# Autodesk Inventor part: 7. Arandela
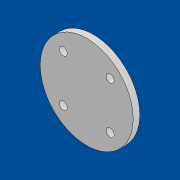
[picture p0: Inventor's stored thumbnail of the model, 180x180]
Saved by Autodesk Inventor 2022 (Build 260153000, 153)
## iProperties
Created: 2022-05
Part Number: 7. Arandela
Material: Genérico
Document SubType Name: Modeling
Designer: pined
Density: 1 g/cm^3
Appearance: Valor por defecto
Author: pined
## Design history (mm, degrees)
sketch "Boceto1" dims "d2" = 25
  geometry: L1 (0, 0)-(0, 25); L2 (0, 0)-(-19.506, 19.506); C1 r 17.5 at (0, 0); C2 r 7.5 at (0, 0); C3 r 1.5 at (-8.839, 8.839); C4 r 1.5 at (-8.839, -8.839); C5 r 1.5 at (8.839, -8.839); C6 r 1.5 at (8.839, 8.839); 1 further point
  constraints: 6 centre point, 4 end point, 3 coincident, 1 point on line, 1 vertical, 12 other
  dimensions: "d0" = 35 diameter of C1; "d1" = 15 diameter of C2; "d3" = 45 deg angle of L1 L2; "d4" = 3 diameter of C3; "d7" = 360 deg dimension on point (0, 0) C3.centre (derived)
extrude "Extrusión1" new body sketch "Boceto1" distance "d9" = 2.5; taper "d10" = 0 deg
node "Sólido1"
